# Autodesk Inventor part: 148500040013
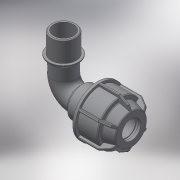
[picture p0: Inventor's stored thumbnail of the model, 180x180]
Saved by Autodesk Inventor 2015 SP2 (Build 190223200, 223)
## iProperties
Created: 2017-08
Part Number: 148500040013
Material: Generic
Description: PLASSON L.14 90° ELBOW MALE ADAPTOR (SILVER) 40-1.1/4"
Document SubType Name: Modeling
Designer: KIM
Density: 1 g/cm^3
Appearance: Default
Author: KIM
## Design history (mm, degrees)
derived "148500.ipt"
feature "Solid1::148500.ipt"
feature "Solid2::148500.ipt"
tag "TaggingFeature1"
body "Solid1"
body "Solid2"
other parameters: "d2" = 62, "d4" = 15 deg, "d5" = 40.92, "d6" = 13.5036, "d10" = 73, "d16" = 40.8, "d17" = 3.1, "d22" = 64, "d24" = 3.1, "d25" = 65.7, "d26" = 54.75, "d27" = 3.1, "d28" = 135 deg, "d29" = 1.86, "d31" = 2, "d46" = 150 deg, "d49" = 3.65, "d50" = 0, "d58" = 1.2, "d61" = 360 deg, "d63" = 36, "d94" = 68, "d96" = 46.101, "d97" = 22, "d98" = 33.528, "d99" = 39.18585, "d100" = 135 deg, "d108" = 2, "d112" = 28.6, "d113" = 86, "d114" = 63.24, "d115" = 39.18585, "d116" = 45 deg, "d117" = 0, "d118" = 0, "d119" = 41.91, "d120" = 22, "d121" = 50.292, "d122" = 23.1, "d123" = 1, "R_" = 41.91, "E_" = 73, "A_" = 86, "l_" = 62, "l_2" = 22, "A_1" = 68
